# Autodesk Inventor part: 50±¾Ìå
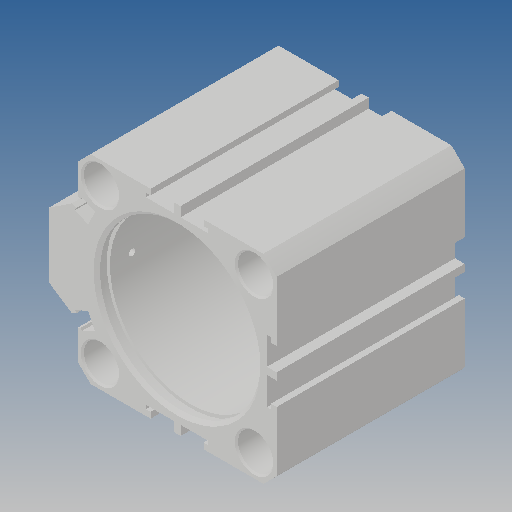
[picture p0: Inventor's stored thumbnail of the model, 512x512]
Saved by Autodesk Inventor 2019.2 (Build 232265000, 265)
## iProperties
Created: 2013-07
Part Number: 50±¾Ìå
Material: Ogólny
Document SubType Name: Modeling
Designer: CADENGINEERING4
Density: 1 g/cm^3
Appearance: Domyślna
Author: CADENGINEERING4
Revision Number: ÈÎºÎ
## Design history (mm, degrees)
feature "µ¹½Ç2"
node "Bryła1"
